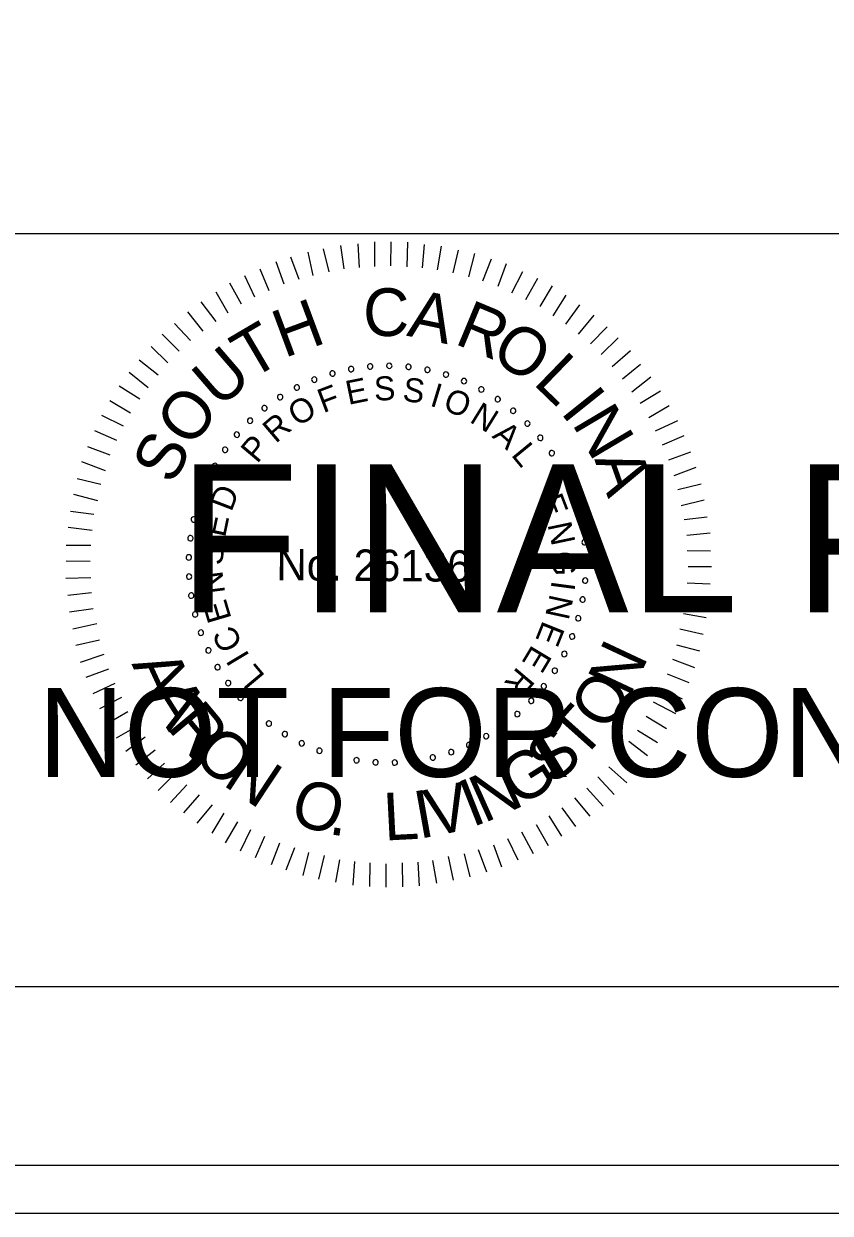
# Model space of a CAD drawing. Extents: x 967 to 1326, y 964 to 3704.
# Drawn here: x 1170.56 to 1189.3, y 1523.72 to 1551.36 of the extents above; entities that cross this region are included whole.
import ezdxf

# ---------------------------------------------------------------- set-up
doc = ezdxf.new("R2010")
doc.units = 0
for name, color, linetype in [('RD_SHT_Bndy', 7, 'Continuous'), ('RD_SHT_IplotShp', 7, 'Continuous'), ('RD_SHT_Misc1', 7, 'Continuous'), ('RD_SHT_Misc2', 7, 'Continuous'), ('RD_XS_TX_Station', 7, 'Continuous')]:
    doc.layers.add(name, color=color, linetype=linetype)

msp = doc.modelspace()

# ---------------------------------------------------------------- linework, layer by layer
at = {"layer": 'RD_SHT_Bndy'}
for p, q in [((996.114, 1546.486), (1323.886, 1546.486)), ((1323.886, 1528.983), (996.114, 1528.983))]:
    msp.add_line(p, q, dxfattribs=at)
at = {"layer": 'RD_SHT_IplotShp'}
for points in [[(967.409, 1523.72), (1326.285, 1523.72), (1326.285, 1743.72), (967.409, 1743.72)], [(988.525, 1524.84), (1326.285, 1524.84), (1326.285, 1742.6), (988.525, 1742.6)]]:
    msp.add_lwpolyline(points, close=True, dxfattribs=at)
at = {"layer": 'RD_SHT_Misc1'}
for p, q in [((1178.01, 1545.663), (1177.93, 1546.209)), ((1178.364, 1545.699), (1178.33, 1546.244)), ((1178.717, 1545.719), (1178.722, 1546.295)), ((1179.093, 1545.739), (1179.098, 1546.292)), ((1179.469, 1545.713), (1179.489, 1546.288)), ((1179.829, 1545.687), (1179.872, 1546.231)), ((1180.174, 1545.646), (1180.271, 1546.19)), ((1176.964, 1545.419), (1176.769, 1545.935)), ((1177.287, 1545.508), (1177.169, 1546.054)), ((1177.657, 1545.597), (1177.53, 1546.128)), ((1180.535, 1545.573), (1180.662, 1546.102)), ((1180.902, 1545.478), (1181.045, 1546.022)), ((1181.231, 1545.384), (1181.428, 1545.896)), ((1176.264, 1545.156), (1176.053, 1545.657)), ((1176.61, 1545.306), (1176.423, 1545.83)), ((1181.584, 1545.265), (1181.78, 1545.786)), ((1175.933, 1545.005), (1175.699, 1545.506)), ((1181.905, 1545.109), (1182.154, 1545.606)), ((1182.226, 1544.953), (1182.506, 1545.45)), ((1175.308, 1544.634), (1175.036, 1545.12)), ((1175.624, 1544.846), (1175.352, 1545.332)), ((1182.562, 1544.789), (1182.85, 1545.27)), ((1175.03, 1544.445), (1174.681, 1544.9)), ((1182.86, 1544.572), (1183.163, 1545.053)), ((1183.158, 1544.378), (1183.484, 1544.828)), ((1174.729, 1544.217), (1174.372, 1544.665)), ((1183.447, 1544.145), (1183.811, 1544.587)), ((1174.435, 1543.997), (1174.062, 1544.399)), ((1183.729, 1543.92), (1184.116, 1544.316)), ((1174.172, 1543.753), (1173.776, 1544.148)), ((1183.98, 1543.672), (1184.368, 1544.061)), ((1173.909, 1543.479), (1173.52, 1543.858)), ((1184.232, 1543.394), (1184.657, 1543.767)), ((1173.684, 1543.197), (1173.242, 1543.546)), ((1184.475, 1543.108), (1184.892, 1543.45)), ((1173.451, 1542.9), (1173.009, 1543.256)), ((1184.687, 1542.807), (1185.128, 1543.156)), ((1173.257, 1542.64), (1172.776, 1542.936)), ((1173.039, 1542.312), (1172.559, 1542.6)), ((1184.885, 1542.544), (1185.355, 1542.832)), ((1185.081, 1542.213), (1185.56, 1542.493)), ((1172.883, 1542.006), (1172.379, 1542.256)), ((1185.24, 1541.904), (1185.756, 1542.145)), ((1172.727, 1541.677), (1172.215, 1541.904)), ((1185.399, 1541.573), (1185.907, 1541.791)), ((1172.571, 1541.333), (1172.051, 1541.53)), ((1185.549, 1541.226), (1186.057, 1541.414)), ((1172.461, 1540.974), (1171.91, 1541.178)), ((1185.669, 1540.865), (1186.185, 1541.06)), ((1172.351, 1540.652), (1171.807, 1540.787)), ((1185.759, 1540.541), (1186.297, 1540.667)), ((1172.286, 1540.276), (1171.727, 1540.419)), ((1185.832, 1540.165), (1186.371, 1540.298)), ((1172.191, 1539.955), (1171.647, 1540.029)), ((1185.906, 1539.842), (1186.436, 1539.906)), ((1172.15, 1539.587), (1171.598, 1539.653)), ((1185.964, 1539.473), (1186.51, 1539.53)), ((1172.124, 1539.234), (1171.548, 1539.239)), ((1185.977, 1539.12), (1186.514, 1539.115)), ((1172.105, 1538.866), (1171.545, 1538.871)), ((1185.997, 1538.751), (1186.542, 1538.747)), ((1172.118, 1538.482), (1171.542, 1538.471)), ((1185.971, 1538.368), (1186.508, 1538.348)), ((1172.138, 1538.136), (1171.585, 1538.072)), ((1185.952, 1538.022), (1186.497, 1537.949)), ((1172.173, 1537.768), (1171.627, 1537.688)), ((1185.888, 1537.655), (1186.417, 1537.566)), ((1172.262, 1537.414), (1171.701, 1537.296)), ((1185.808, 1537.302), (1186.345, 1537.175)), ((1172.321, 1537.037), (1171.774, 1536.911)), ((1185.729, 1536.926), (1186.265, 1536.792)), ((1172.425, 1536.707), (1171.871, 1536.519)), ((1185.634, 1536.597), (1186.146, 1536.401)), ((1172.53, 1536.36), (1172.007, 1536.173)), ((1185.508, 1536.253), (1186.013, 1536.057)), ((1172.681, 1536.029), (1172.165, 1535.788)), ((1172.831, 1535.705), (1172.323, 1535.441)), ((1185.352, 1535.924), (1185.857, 1535.675)), ((1185.188, 1535.603), (1185.7, 1535.33)), ((1172.982, 1535.374), (1172.497, 1535.094)), ((1185.024, 1535.274), (1185.498, 1534.987)), ((1173.194, 1535.042), (1172.709, 1534.762)), ((1184.822, 1534.946), (1185.288, 1534.658)), ((1173.384, 1534.78), (1172.936, 1534.453)), ((1184.62, 1534.687), (1185.055, 1534.353)), ((1173.612, 1534.478), (1173.164, 1534.129)), ((1184.403, 1534.389), (1184.814, 1534.033)), ((1173.832, 1534.177), (1173.437, 1533.812)), ((1184.155, 1534.092), (1184.574, 1533.72)), ((1174.091, 1533.945), (1173.689, 1533.541)), ((1183.899, 1533.864), (1184.28, 1533.454)), ((1174.35, 1533.674), (1173.97, 1533.263)), ((1183.644, 1533.597), (1184.024, 1533.18)), ((1174.64, 1533.442), (1174.275, 1533.022)), ((1174.937, 1533.209), (1174.58, 1532.782)), ((1183.358, 1533.37), (1183.715, 1532.944)), ((1175.212, 1533.014), (1174.932, 1532.549)), ((1182.764, 1532.952), (1183.059, 1532.482)), ((1183.065, 1533.141), (1183.384, 1532.709)), ((1175.525, 1532.812), (1175.245, 1532.331)), ((1175.83, 1532.633), (1175.588, 1532.136)), ((1182.463, 1532.755), (1182.743, 1532.269)), ((1176.159, 1532.477), (1175.94, 1531.98)), ((1181.8, 1532.431), (1182.041, 1531.93)), ((1182.124, 1532.581), (1182.396, 1532.08)), ((1176.503, 1532.321), (1176.307, 1531.816)), ((1176.855, 1532.211), (1176.651, 1531.69)), ((1177.177, 1532.1), (1177.05, 1531.572)), ((1181.122, 1532.175), (1181.31, 1531.652)), ((1181.476, 1532.28), (1181.664, 1531.771)), ((1177.545, 1532.036), (1177.409, 1531.484)), ((1177.897, 1531.933), (1177.808, 1531.412)), ((1178.25, 1531.892), (1178.207, 1531.34)), ((1178.603, 1531.866), (1178.598, 1531.313)), ((1178.978, 1531.84), (1178.974, 1531.295)), ((1179.355, 1531.86), (1179.365, 1531.307)), ((1179.715, 1531.88), (1179.749, 1531.327)), ((1180.061, 1531.915), (1180.149, 1531.393)), ((1180.423, 1532.012), (1180.541, 1531.458)), ((1180.791, 1532.07), (1180.926, 1531.54))]:
    msp.add_line(p, q, dxfattribs=at)
for centre, start, end in [((1178.609, 1543.397), 5.0653, 185.0653), ((1179.055, 1543.414), 359.5268, 179.5268), ((1179.055, 1543.414), 179.5268, 359.5268), ((1179.5, 1543.388), 353.9884, 173.9884), ((1177.312, 1543.091), 21.6807, 201.6807), ((1177.734, 1543.235), 16.1422, 196.1422), ((1177.734, 1543.235), 196.1422, 16.1422), ((1178.168, 1543.337), 10.6038, 190.6038), ((1178.168, 1543.337), 190.6038, 10.6038), ((1178.609, 1543.397), 185.0653, 5.0653), ((1179.5, 1543.388), 173.9884, 353.9884), ((1179.94, 1543.319), 168.4499, 348.4499), ((1179.94, 1543.319), 348.4499, 168.4499), ((1180.372, 1543.208), 162.9114, 342.9114), ((1180.372, 1543.208), 342.9114, 162.9114), ((1176.906, 1542.908), 27.2191, 207.2191), ((1176.906, 1542.908), 207.2191, 27.2191), ((1177.312, 1543.091), 201.6807, 21.6807), ((1180.79, 1543.056), 157.373, 337.373), ((1180.79, 1543.056), 337.373, 157.373), ((1181.193, 1542.864), 151.8345, 331.8345), ((1181.193, 1542.864), 331.8345, 151.8345), ((1176.52, 1542.686), 32.7576, 212.7576), ((1176.52, 1542.686), 212.7576, 32.7576), ((1181.574, 1542.634), 146.2961, 326.2961), ((1181.574, 1542.634), 326.2961, 146.2961), ((1176.156, 1542.428), 38.2961, 218.2961), ((1176.156, 1542.428), 218.2961, 38.2961), ((1181.932, 1542.368), 140.7576, 320.7576), ((1181.932, 1542.368), 320.7576, 140.7576), ((1175.82, 1542.135), 43.8345, 223.8345), ((1175.82, 1542.135), 223.8345, 43.8345), ((1182.263, 1542.069), 135.2191, 315.2191), ((1182.263, 1542.069), 315.2191, 135.2191), ((1175.513, 1541.812), 49.373, 229.373), ((1175.513, 1541.812), 229.373, 49.373), ((1182.563, 1541.74), 129.6807, 309.6807), ((1182.563, 1541.74), 309.6807, 129.6807), ((1175.239, 1541.461), 54.9114, 234.9114), ((1175.239, 1541.461), 234.9114, 54.9114), ((1182.83, 1541.383), 124.1422, 304.1422), ((1182.83, 1541.383), 304.1422, 124.1422), ((1175, 1541.085), 60.4499, 240.4499), ((1175, 1541.085), 240.4499, 60.4499), ((1183.061, 1541.002), 118.6038, 298.6038), ((1183.061, 1541.002), 298.6038, 118.6038), ((1174.798, 1540.687), 65.9884, 245.9884), ((1174.798, 1540.687), 245.9884, 65.9884), ((1183.255, 1540.601), 113.0653, 293.0653), ((1183.255, 1540.601), 293.0653, 113.0653), ((1174.636, 1540.272), 71.5268, 251.5268), ((1174.636, 1540.272), 251.5268, 71.5268), ((1183.408, 1540.182), 107.5268, 287.5268), ((1183.408, 1540.182), 287.5268, 107.5268), ((1174.514, 1539.843), 77.0653, 257.0653), ((1174.514, 1539.843), 257.0653, 77.0653), ((1183.521, 1539.751), 101.9884, 281.9884), ((1183.521, 1539.751), 281.9884, 101.9884), ((1174.435, 1539.405), 82.6038, 262.6038), ((1174.435, 1539.405), 262.6038, 82.6038), ((1183.592, 1539.311), 96.4499, 276.4499), ((1183.592, 1539.311), 276.4499, 96.4499), ((1174.398, 1538.961), 88.1422, 268.1422), ((1174.398, 1538.961), 268.1422, 88.1422), ((1183.619, 1538.866), 90.9114, 270.9114), ((1183.619, 1538.866), 270.9114, 90.9114), ((1174.404, 1538.515), 93.6807, 273.6807), ((1174.404, 1538.515), 273.6807, 93.6807), ((1183.604, 1538.421), 85.373, 265.373), ((1183.604, 1538.421), 265.373, 85.373), ((1174.453, 1538.072), 99.2191, 279.2191), ((1174.453, 1538.072), 279.2191, 99.2191), ((1183.546, 1537.979), 79.8345, 259.8345), ((1183.546, 1537.979), 259.8345, 79.8345), ((1174.545, 1537.636), 104.7576, 284.7576), ((1174.545, 1537.636), 284.7576, 104.7576), ((1183.445, 1537.545), 74.2961, 254.2961), ((1183.445, 1537.545), 254.2961, 74.2961), ((1174.678, 1537.211), 110.2961, 290.2961), ((1174.678, 1537.211), 290.2961, 110.2961), ((1183.303, 1537.122), 68.7576, 248.7576), ((1183.303, 1537.122), 248.7576, 68.7576), ((1174.852, 1536.8), 115.8345, 295.8345), ((1174.852, 1536.8), 295.8345, 115.8345), ((1183.121, 1536.716), 63.2191, 243.2191), ((1183.121, 1536.716), 243.2191, 63.2191), ((1175.065, 1536.409), 121.373, 301.373), ((1175.065, 1536.409), 301.373, 121.373), ((1182.9, 1536.328), 57.6807, 237.6807), ((1182.9, 1536.328), 237.6807, 57.6807), ((1175.314, 1536.039), 126.9114, 306.9114), ((1175.314, 1536.039), 306.9114, 126.9114), ((1182.643, 1535.964), 52.1422, 232.1422), ((1182.643, 1535.964), 232.1422, 52.1422), ((1175.598, 1535.696), 132.4499, 312.4499), ((1175.598, 1535.696), 312.4499, 132.4499), ((1182.353, 1535.627), 46.6038, 226.6038), ((1182.353, 1535.627), 226.6038, 46.6038), ((1175.914, 1535.381), 137.9884, 317.9884), ((1175.914, 1535.381), 317.9884, 137.9884), ((1176.258, 1535.099), 143.5268, 323.5268), ((1176.258, 1535.099), 323.5268, 143.5268), ((1182.03, 1535.319), 41.0653, 221.0653), ((1182.03, 1535.319), 221.0653, 41.0653), ((1176.629, 1534.851), 149.0653, 329.0653), ((1176.629, 1534.851), 329.0653, 149.0653), ((1181.305, 1534.803), 29.9884, 209.9884), ((1181.68, 1535.043), 35.5268, 215.5268), ((1181.68, 1535.043), 215.5268, 35.5268), ((1177.021, 1534.639), 154.6038, 334.6038), ((1177.021, 1534.639), 334.6038, 154.6038), ((1180.908, 1534.6), 24.4499, 204.4499), ((1180.908, 1534.6), 204.4499, 24.4499), ((1181.305, 1534.803), 209.9884, 29.9884), ((1177.432, 1534.467), 160.1422, 340.1422), ((1177.432, 1534.467), 340.1422, 160.1422), ((1177.858, 1534.335), 165.6807, 345.6807), ((1177.858, 1534.335), 345.6807, 165.6807), ((1178.294, 1534.245), 351.2191, 171.2191), ((1179.627, 1534.232), 7.8345, 187.8345), ((1180.065, 1534.313), 13.373, 193.373), ((1180.065, 1534.313), 193.373, 13.373), ((1180.494, 1534.436), 18.9114, 198.9114), ((1180.494, 1534.436), 198.9114, 18.9114), ((1178.294, 1534.245), 171.2191, 351.2191), ((1178.737, 1534.198), 356.7576, 176.7576), ((1178.737, 1534.198), 176.7576, 356.7576), ((1179.183, 1534.193), 2.2961, 182.2961), ((1179.183, 1534.193), 182.2961, 2.2961), ((1179.627, 1534.232), 187.8345, 7.8345)]:
    msp.add_arc(centre, 0.0627, start, end, dxfattribs=at)
at = {"layer": 'RD_XS_TX_Station'}
msp.add_lwpolyline([(967.409, 1523.72), (1326.285, 1523.72), (1326.285, 1743.72), (967.409, 1743.72)], close=True, dxfattribs=at)

# ---------------------------------------------------------------- texts
at = {"layer": 'RD_SHT_Misc1'}
for s, height, rotation, p in [('C', 1.11, 359.5482, (1178.442, 1544.108)), ('A', 1.11, 348.1981, (1179.439, 1544.115)), ('H', 1.11, 20.3637, (1176.614, 1543.587)), ('R', 1.11, 337.4344, (1180.541, 1543.937)), ('T', 1.11, 30.4992, (1175.828, 1543.072)), ('O', 1.108, 326.5869, (1181.366, 1543.609)), ('U', 1.11, 40.8022, (1175.102, 1542.403)), ('L', 1.11, 315.9488, (1182.373, 1543.003)), ('E', 0.557, 11.4103, (1178.103, 1542.503)), ('S', 0.557, 2.208, (1178.709, 1542.601)), ('S', 0.557, 352.6608, (1179.346, 1542.599)), ('F', 0.557, 20.6127, (1177.52, 1542.309)), ('I', 0.557, 343.1136, (1179.975, 1542.491)), ('O', 0.557, 338.4392, (1180.274, 1542.401)), ('I', 1.11, 308.6613, (1183.011, 1542.338)), ('O', 1.11, 52.0267, (1174.435, 1541.474)), ('O', 0.557, 30.8477, (1176.917, 1541.987)), ('N', 0.557, 328.2042, (1180.896, 1542.12)), ('N', 1.11, 300.7037, (1183.285, 1542.075)), ('R', 0.557, 40.3949, (1176.415, 1541.594)), ('A', 0.557, 318.657, (1181.424, 1541.762)), ('S', 1.108, 63.2511, (1174.029, 1540.619)), ('P', 0.557, 49.9421, (1175.985, 1541.124)), ('L', 0.557, 309.4546, (1181.869, 1541.339)), ('A', 1.11, 289.4792, (1183.814, 1541.243)), ('D', 0.557, 69.0364, (1175.386, 1540.003)), ('E', 0.557, 291.049, (1182.53, 1540.307)), ('E', 0.557, 78.2388, (1175.238, 1539.407)), ('N', 0.557, 281.8466, (1182.728, 1539.726)), ('S', 0.557, 87.786, (1175.187, 1538.772)), ('No. 26136', 0.7311, 359.5268, (1176.429, 1538.43)), ('G', 0.557, 272.2995, (1182.833, 1539.097)), ('N', 0.557, 97.3332, (1175.242, 1538.137)), ('I', 0.557, 262.4084, (1182.83, 1538.437)), ('E', 0.557, 106.5355, (1175.394, 1537.541)), ('N', 0.557, 257.7339, (1182.789, 1538.127)), ('C', 0.557, 116.4266, (1175.661, 1536.938)), ('E', 0.557, 248.1867, (1182.628, 1537.511)), ('I', 0.557, 121.1011, (1175.823, 1536.67)), ('E', 0.557, 238.9844, (1182.378, 1536.949)), ('N', 1.105, 64.8922, (1184.632, 1535.684)), ('A', 1.105, 294.7297, (1173.062, 1536.486)), ('L', 0.557, 129.9595, (1176.187, 1536.204)), ('R', 0.557, 229.782, (1182.041, 1536.435)), ('O', 1.105, 56.2059, (1184.102, 1534.874)), ('A', 1.105, 302.2892, (1173.414, 1535.72)), ('R', 1.105, 309.8487, (1173.865, 1535.007)), ('T', 1.105, 48.2685, (1183.515, 1534.211)), ('O', 1.105, 317.7861, (1174.434, 1534.33)), ('S', 1.105, 40.3311, (1182.842, 1533.636)), ('N', 1.105, 326.4725, (1175.158, 1533.686)), ('G', 1.105, 32.0198, (1182.059, 1533.14)), ('N', 1.105, 24.0824, (1181.252, 1532.776)), ('O', 1.105, 342.3472, (1176.697, 1532.82)), ('V', 1.105, 12.7741, (1180.033, 1532.457)), ('I', 1.105, 21.4605, (1180.976, 1532.681)), ('L', 1.105, 2.9677, (1178.943, 1532.379)), ('I', 1.105, 10.1523, (1179.743, 1532.418)), ('.', 1.105, 351.0336, (1177.623, 1532.536))]:
    msp.add_text(s, height=height, rotation=rotation, dxfattribs=at).set_placement(p)
at = {"layer": 'RD_SHT_Misc2'}
for s, height, p in [('FINAL PLANS', 3.4375, (1174.145, 1537.685)), ('NOT FOR CONSTRUCTION', 2.0625, (1170.901, 1533.86))]:
    msp.add_text(s, height=height, dxfattribs=at).set_placement(p)

doc.saveas('drawing.dxf')
